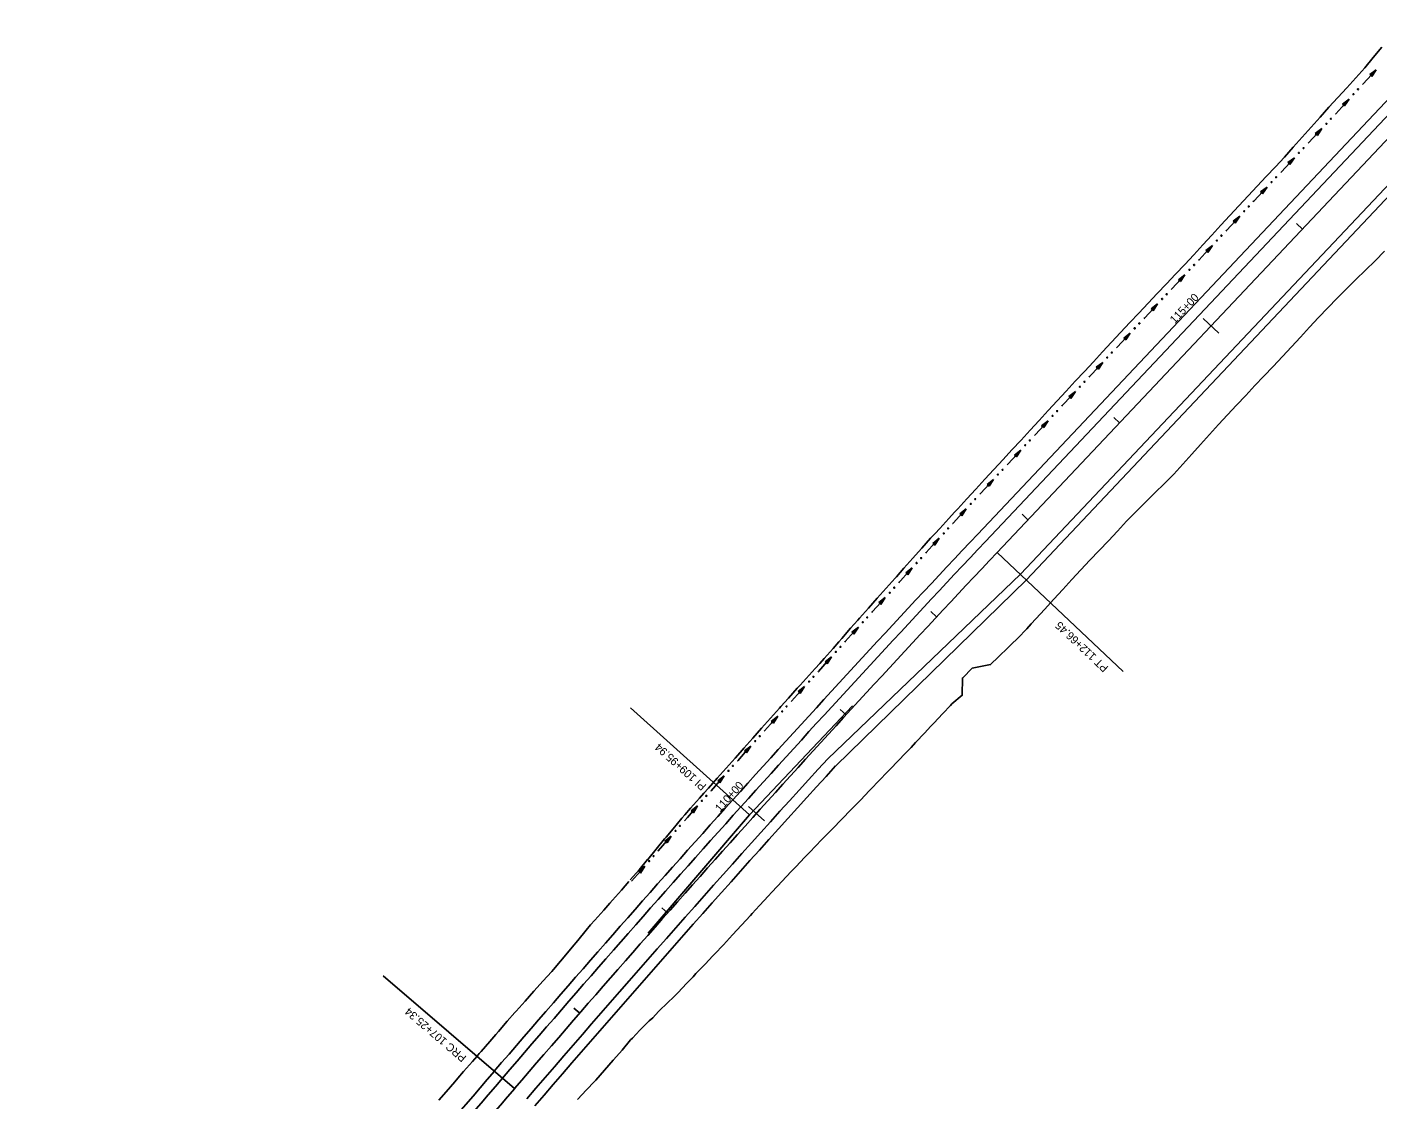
# Model space of a CAD drawing. Extents: x 1375694 to 1433473, y 1931050 to 1967991.
# Drawn here: x 1375783 to 1376795, y 1931542 to 1932347 of the extents above; entities that cross this region are included whole.
import ezdxf

# ---------------------------------------------------------------- set-up
doc = ezdxf.new("R2010")
doc.units = 0
for name, color, linetype in [('62', 7, 'Continuous'), ('R_Horz Alg', 7, 'Continuous'), ('R_Horz Alg Annot', 7, 'Continuous'), ('R_Proposed Const Limits', 7, 'Continuous'), ('R_Proposed Road', 7, 'Continuous')]:
    doc.layers.add(name, color=color, linetype=linetype)

msp = doc.modelspace()

# ---------------------------------------------------------------- linework, layer by layer
at = {"layer": '62'}
for p, q in [((1376794.8, 1932314.4), (1376789.9, 1932310.8)), ((1376789.9, 1932310.8), (1376791.5, 1932309.3)), ((1376791.5, 1932309.3), (1376794.8, 1932314.4)), ((1376774.4, 1932292.4), (1376769.5, 1932288.7)), ((1376769.5, 1932288.7), (1376771.1, 1932287.3)), ((1376771.1, 1932287.3), (1376774.4, 1932292.4)), ((1376754, 1932270.3), (1376749.1, 1932266.7)), ((1376749.1, 1932266.7), (1376750.7, 1932265.2)), ((1376750.7, 1932265.2), (1376754, 1932270.3)), ((1376733.4, 1932248.4), (1376728.6, 1932244.8)), ((1376728.6, 1932244.8), (1376730.1, 1932243.3)), ((1376730.1, 1932243.3), (1376733.4, 1932248.4)), ((1376712.9, 1932226.5), (1376708, 1932222.9)), ((1376709.6, 1932221.4), (1376712.9, 1932226.5)), ((1376708, 1932222.9), (1376709.6, 1932221.4)), ((1376692.4, 1932204.6), (1376687.5, 1932200.9)), ((1376689, 1932199.5), (1376692.4, 1932204.6)), ((1376687.5, 1932200.9), (1376689, 1932199.5)), ((1376671.9, 1932182.6), (1376667, 1932179)), ((1376667, 1932179), (1376668.5, 1932177.5)), ((1376668.5, 1932177.5), (1376671.9, 1932182.6)), ((1376651.3, 1932160.7), (1376646.5, 1932157)), ((1376646.5, 1932157), (1376648, 1932155.6)), ((1376648, 1932155.6), (1376651.3, 1932160.7)), ((1376630.8, 1932138.8), (1376625.9, 1932135.1)), ((1376625.9, 1932135.1), (1376627.5, 1932133.7)), ((1376627.5, 1932133.7), (1376630.8, 1932138.8)), ((1376610.3, 1932116.9), (1376605.4, 1932113.2)), ((1376605.4, 1932113.2), (1376606.9, 1932111.8)), ((1376606.9, 1932111.8), (1376610.3, 1932116.9)), ((1376589.7, 1932095), (1376584.8, 1932091.3)), ((1376586.4, 1932089.9), (1376589.7, 1932095)), ((1376584.8, 1932091.3), (1376586.4, 1932089.9)), ((1376569.2, 1932073), (1376564.3, 1932069.4)), ((1376565.8, 1932067.9), (1376569.2, 1932073)), ((1376564.3, 1932069.4), (1376565.8, 1932067.9)), ((1376548.7, 1932051.1), (1376543.8, 1932047.4)), ((1376543.8, 1932047.4), (1376545.4, 1932046)), ((1376545.4, 1932046), (1376548.7, 1932051.1)), ((1376528.2, 1932029.1), (1376523.4, 1932025.4)), ((1376523.4, 1932025.4), (1376524.9, 1932024)), ((1376524.9, 1932024), (1376528.2, 1932029.1)), ((1376507.8, 1932007.1), (1376502.9, 1932003.4)), ((1376502.9, 1932003.4), (1376504.5, 1932002)), ((1376504.5, 1932002), (1376507.8, 1932007.1)), ((1376487.3, 1931985.1), (1376482.5, 1931981.4)), ((1376482.5, 1931981.4), (1376484, 1931979.9)), ((1376484, 1931979.9), (1376487.3, 1931985.1)), ((1376467, 1931963), (1376462.2, 1931959.2)), ((1376463.7, 1931957.8), (1376467, 1931963)), ((1376462.2, 1931959.2), (1376463.7, 1931957.8)), ((1376446.8, 1931940.8), (1376441.9, 1931937)), ((1376443.5, 1931935.6), (1376446.8, 1931940.8)), ((1376441.9, 1931937), (1376443.5, 1931935.6)), ((1376426.6, 1931918.5), (1376421.8, 1931914.8)), ((1376421.8, 1931914.8), (1376423.3, 1931913.3)), ((1376423.3, 1931913.3), (1376426.6, 1931918.5)), ((1376406.4, 1931896.3), (1376401.5, 1931892.6)), ((1376401.5, 1931892.6), (1376403.1, 1931891.2)), ((1376403.1, 1931891.2), (1376406.4, 1931896.3)), ((1376386.2, 1931874.1), (1376381.4, 1931870.3)), ((1376381.4, 1931870.3), (1376382.9, 1931868.9)), ((1376382.9, 1931868.9), (1376386.2, 1931874.1)), ((1376366, 1931851.8), (1376361.2, 1931848)), ((1376362.8, 1931846.6), (1376366, 1931851.8)), ((1376361.2, 1931848), (1376362.8, 1931846.6)), ((1376345.9, 1931829.5), (1376341.1, 1931825.7)), ((1376342.7, 1931824.3), (1376345.9, 1931829.5)), ((1376341.1, 1931825.7), (1376342.7, 1931824.3)), ((1376325.8, 1931807.2), (1376320.9, 1931803.5)), ((1376320.9, 1931803.5), (1376322.5, 1931802)), ((1376322.5, 1931802), (1376325.8, 1931807.2)), ((1376305.7, 1931784.8), (1376301, 1931781)), ((1376301, 1931781), (1376302.5, 1931779.6)), ((1376302.5, 1931779.6), (1376305.7, 1931784.8)), ((1376285.8, 1931762.3), (1376281.1, 1931758.5)), ((1376281.1, 1931758.5), (1376282.7, 1931757.1)), ((1376282.7, 1931757.1), (1376285.8, 1931762.3)), ((1376266, 1931739.7), (1376261.3, 1931735.9)), ((1376262.9, 1931734.5), (1376266, 1931739.7)), ((1376261.3, 1931735.9), (1376262.9, 1931734.5)), ((1376246.2, 1931717.1), (1376241.5, 1931713.3)), ((1376241.5, 1931713.3), (1376243.1, 1931711.9)), ((1376243.1, 1931711.9), (1376246.2, 1931717.1))]:
    msp.add_line(p, q, dxfattribs=at)
for points in [[(1376784.6, 1932303.5), (1376784.7, 1932303.6), (1376791.5, 1932310.9), (1376794.8, 1932314.4)], [(1376784.5, 1932303.4), (1376784.6, 1932303.5)], [(1376764.2, 1932281.3), (1376764.4, 1932281.5), (1376771.2, 1932288.9), (1376774.4, 1932292.4)], [(1376764.2, 1932281.3), (1376764.2, 1932281.3)], [(1376743.7, 1932259.4), (1376743.9, 1932259.6), (1376750.8, 1932266.9), (1376754, 1932270.3)], [(1376743.7, 1932259.4), (1376743.7, 1932259.4)], [(1376723.2, 1932237.5), (1376723.4, 1932237.7), (1376730.2, 1932245), (1376733.4, 1932248.4)], [(1376723.2, 1932237.5), (1376723.2, 1932237.5)], [(1376702.6, 1932215.6), (1376702.9, 1932215.8), (1376709.7, 1932223.1), (1376712.9, 1932226.5)], [(1376702.6, 1932215.5), (1376702.6, 1932215.6)], [(1376682.1, 1932193.6), (1376682.4, 1932193.9), (1376689.2, 1932201.2), (1376692.4, 1932204.6)], [(1376682.1, 1932193.6), (1376682.1, 1932193.6)], [(1376661.6, 1932171.7), (1376661.9, 1932172), (1376668.7, 1932179.3), (1376671.9, 1932182.6)], [(1376661.6, 1932171.6), (1376661.6, 1932171.7)], [(1376641.1, 1932149.7), (1376641.4, 1932150.1), (1376648.2, 1932157.4), (1376651.3, 1932160.7)], [(1376641.1, 1932149.7), (1376641.1, 1932149.7)], [(1376620.5, 1932127.8), (1376620.9, 1932128.2), (1376627.7, 1932135.5), (1376630.8, 1932138.8)], [(1376620.5, 1932127.8), (1376620.5, 1932127.8)], [(1376600, 1932105.9), (1376600.4, 1932106.3), (1376607.2, 1932113.6), (1376610.3, 1932116.9)], [(1376600, 1932105.9), (1376600, 1932105.9)], [(1376579.4, 1932084), (1376579.8, 1932084.4), (1376586.7, 1932091.7), (1376589.7, 1932095)], [(1376579.4, 1932084), (1376579.4, 1932084)], [(1376558.9, 1932062.1), (1376559.3, 1932062.5), (1376566.2, 1932069.8), (1376569.2, 1932073)], [(1376558.9, 1932062.1), (1376558.9, 1932062.1)], [(1376538.4, 1932040.1), (1376538.9, 1932040.6), (1376545.7, 1932047.9), (1376548.7, 1932051.1)], [(1376538.4, 1932040.1), (1376538.4, 1932040.1)], [(1376518, 1932018.1), (1376518.5, 1932018.6), (1376525.3, 1932025.9), (1376528.2, 1932029.1)], [(1376518, 1932018.1), (1376518, 1932018.1)], [(1376497.6, 1931996.1), (1376498, 1931996.6), (1376504.8, 1932003.9), (1376507.8, 1932007.1)], [(1376497.5, 1931996.1), (1376497.6, 1931996.1)], [(1376477.2, 1931974), (1376477.7, 1931974.6), (1376482, 1931979.3), (1376484.4, 1931982), (1376487.3, 1931985.1)], [(1376477.1, 1931974), (1376477.2, 1931974)], [(1376456.9, 1931951.9), (1376457.3, 1931952.4), (1376464.1, 1931959.8), (1376467, 1931963)], [(1376456.9, 1931951.9), (1376456.9, 1931951.9)], [(1376436.7, 1931929.7), (1376437.1, 1931930.1), (1376438.1, 1931931.2), (1376443.8, 1931937.5), (1376446.8, 1931940.8)], [(1376436.7, 1931929.6), (1376436.7, 1931929.7)], [(1376416.5, 1931907.4), (1376416.8, 1931907.8), (1376423.5, 1931915.1), (1376423.6, 1931915.2), (1376426.6, 1931918.5)], [(1376416.5, 1931907.4), (1376416.5, 1931907.4)], [(1376396.3, 1931885.2), (1376396.6, 1931885.6), (1376403.3, 1931893), (1376406.4, 1931896.3)], [(1376396.2, 1931885.2), (1376396.3, 1931885.2)], [(1376376.1, 1931862.9), (1376376.4, 1931863.2), (1376379.7, 1931866.9), (1376383.1, 1931870.7), (1376386.2, 1931874.1)], [(1376376.1, 1931862.9), (1376376.1, 1931862.9)], [(1376356, 1931840.6), (1376356.2, 1931840.9), (1376362.9, 1931848.3), (1376365.2, 1931850.8), (1376366, 1931851.8)], [(1376356, 1931840.6), (1376356, 1931840.6)], [(1376335.8, 1931818.3), (1376336, 1931818.6), (1376336, 1931818.6), (1376342.8, 1931826), (1376345.9, 1931829.5)], [(1376335.8, 1931818.3), (1376335.8, 1931818.3)], [(1376315.7, 1931796.1), (1376315.9, 1931796.2), (1376321.5, 1931802.5), (1376322.6, 1931803.7), (1376325.8, 1931807.2)], [(1376315.7, 1931796), (1376315.7, 1931796.1)], [(1376295.8, 1931773.6), (1376295.9, 1931773.7), (1376302.5, 1931781.2), (1376305.7, 1931784.8)], [(1376295.8, 1931773.5), (1376295.8, 1931773.6)], [(1376275.9, 1931751), (1376276, 1931751.1), (1376278.3, 1931753.7), (1376282.6, 1931758.6), (1376285.8, 1931762.3)], [(1376275.9, 1931751), (1376275.9, 1931751)], [(1376256.1, 1931728.4), (1376256.2, 1931728.5), (1376262.8, 1931736), (1376264, 1931737.4), (1376266, 1931739.7)], [(1376256.1, 1931728.4), (1376256.1, 1931728.4)], [(1376236.3, 1931705.9), (1376243, 1931713.4), (1376246.2, 1931717.1)]]:
    msp.add_lwpolyline(points, dxfattribs=at)
for centre in [(1376777.7, 1932296.1), (1376781.1, 1932299.8), (1376757.4, 1932274), (1376760.8, 1932277.7), (1376740.3, 1932255.7), (1376736.8, 1932252.1), (1376719.7, 1932233.8), (1376716.3, 1932230.2), (1376695.8, 1932208.3), (1376699.2, 1932211.9), (1376675.3, 1932186.3), (1376678.7, 1932190), (1376654.7, 1932164.4), (1376658.2, 1932168), (1376634.2, 1932142.5), (1376637.6, 1932146.1), (1376617.1, 1932124.2), (1376613.6, 1932120.5), (1376596.5, 1932102.3), (1376593.1, 1932098.6), (1376572.6, 1932076.7), (1376576, 1932080.4), (1376552.1, 1932054.8), (1376555.5, 1932058.4), (1376531.6, 1932032.8), (1376535, 1932036.4), (1376511.1, 1932010.8), (1376514.6, 1932014.4), (1376494.1, 1931992.4), (1376490.7, 1931988.8), (1376473.7, 1931970.4), (1376470.4, 1931966.7), (1376450.1, 1931944.5), (1376453.5, 1931948.2), (1376429.9, 1931922.2), (1376433.3, 1931926), (1376409.7, 1931900), (1376413.1, 1931903.7), (1376392.9, 1931881.5), (1376389.5, 1931877.8), (1376372.7, 1931859.2), (1376369.4, 1931855.5), (1376349.3, 1931833.2), (1376352.6, 1931836.9), (1376329.1, 1931810.9), (1376332.4, 1931814.6), (1376309, 1931788.6), (1376312.3, 1931792.3), (1376292.4, 1931769.8), (1376289.1, 1931766.1), (1376269.3, 1931743.5), (1376272.6, 1931747.3), (1376249.5, 1931720.9), (1376252.8, 1931724.7)]:
    msp.add_circle(centre, 0.375, dxfattribs=at)
at = {"layer": 'R_Horz Alg'}
msp.add_line((1376510.6, 1931952.4), (1377531.3, 1933034.1), dxfattribs=at)
for centre, start, end in [((1384844.8, 1924087.8), 136.66069, 139.36624), ((1367452.4, 1939012.7), 316.73955, 319.36624)]:
    msp.add_arc(centre, 11459.2, start, end, dxfattribs=at)
at = {"layer": 'R_Horz Alg Annot'}
for p, q in [((1376402, 1931837.4), (1376324.8, 1931755.6)), ((1376324.8, 1931755.6), (1376248.7, 1931666.9))]:
    msp.add_line(p, q, dxfattribs=at)
for points in [[(1376735.1, 1932199.1), (1376739.5, 1932195)], [(1376665, 1932127.8), (1376676.7, 1932116.8)], [(1376597.9, 1932053.7), (1376602.2, 1932049.6)], [(1376529.2, 1931981), (1376533.6, 1931976.8)], [(1376510.6, 1931952.4), (1376605.1, 1931863.2)], [(1376460.7, 1931908.1), (1376465.1, 1931904)], [(1376324.8, 1931755.6), (1376235.6, 1931835.9)], [(1376392.8, 1931834.6), (1376397.2, 1931830.5)], [(1376324, 1931761.9), (1376335.9, 1931751.2)], [(1376258.9, 1931685.9), (1376263.4, 1931681.9)], [(1376148.6, 1931550.3), (1376050, 1931634.9)], [(1376192.9, 1931610.7), (1376197.4, 1931606.8)]]:
    msp.add_lwpolyline(points, dxfattribs=at)
at = {"layer": 'R_Proposed Const Limits'}
for points in [[(1376235.2, 1931706.9), (1376241.9, 1931714.4), (1376248.3, 1931722.1), (1376248.4, 1931722.2), (1376254.7, 1931729.8), (1376261.1, 1931737.5), (1376262.3, 1931738.9), (1376267.5, 1931745.2), (1376273.9, 1931753), (1376276.2, 1931755.6), (1376280.5, 1931760.5), (1376287.2, 1931768), (1376290.6, 1931771.8), (1376293.9, 1931775.5), (1376300.5, 1931783), (1376305, 1931788.1), (1376307.2, 1931790.5), (1376313.9, 1931798), (1376319.4, 1931804.3), (1376320.5, 1931805.5), (1376327.2, 1931813.1), (1376333.8, 1931820.6), (1376333.8, 1931820.6), (1376340.5, 1931828.1), (1376347.2, 1931835.5), (1376348.3, 1931836.8), (1376353.9, 1931843), (1376360.6, 1931850.5), (1376362.8, 1931852.9), (1376367.3, 1931857.9), (1376374, 1931865.4), (1376377.4, 1931869.1), (1376380.8, 1931872.8), (1376387.4, 1931880.4), (1376391.7, 1931885.4), (1376394, 1931887.9), (1376400.6, 1931895.5), (1376406.1, 1931901.7), (1376407.3, 1931903), (1376413.9, 1931910.5), (1376420.5, 1931918), (1376420.6, 1931918.1), (1376427.2, 1931925.6), (1376433.9, 1931933.1), (1376434.9, 1931934.2), (1376440.5, 1931940.6), (1376447.2, 1931948.1), (1376449.3, 1931950.4), (1376453.9, 1931955.6), (1376460.6, 1931963), (1376463.9, 1931966.6), (1376467.4, 1931970.4), (1376474.2, 1931977.9), (1376478.5, 1931982.6), (1376481, 1931985.2), (1376487.7, 1931992.6), (1376494.5, 1931999.9), (1376501.3, 1932007.3), (1376508.1, 1932014.6), (1376514.9, 1932022), (1376521.6, 1932029.4), (1376528.4, 1932036.7), (1376535.2, 1932044.1), (1376542, 1932051.4), (1376548.8, 1932058.8), (1376555.5, 1932066.1), (1376562.3, 1932073.4), (1376569.1, 1932080.8), (1376575.9, 1932088.1), (1376582.7, 1932095.5), (1376589.5, 1932102.8), (1376596.3, 1932110.1), (1376603.1, 1932117.5), (1376609.9, 1932124.8), (1376616.8, 1932132), (1376623.7, 1932139.3), (1376630.6, 1932146.6), (1376637.4, 1932153.8), (1376644.3, 1932161.1), (1376651.2, 1932168.4), (1376657.9, 1932175.7), (1376664.7, 1932183.1), (1376671.5, 1932190.4), (1376678.2, 1932197.8), (1376685, 1932205.2), (1376691.8, 1932212.5), (1376698.7, 1932219.8), (1376705.5, 1932227.1), (1376712.3, 1932234.4), (1376719.2, 1932241.7), (1376726, 1932249), (1376732.6, 1932256.5), (1376739.3, 1932263.9), (1376746.1, 1932271.3), (1376752.7, 1932278.8), (1376759.3, 1932286.3), (1376766.1, 1932293.7), (1376772.8, 1932301), (1376779.5, 1932308.5), (1376786.2, 1932315.9), (1376792.5, 1932323.7), (1376799.1, 1932331.3)], [(1376491.8, 1931865.5), (1376505.5, 1931868.3), (1376511.6, 1931874.2), (1376518.8, 1931881.1), (1376521, 1931883.3), (1376525.9, 1931888.1), (1376532.8, 1931895.2), (1376536, 1931898.8), (1376539.5, 1931902.6), (1376546.3, 1931909.9), (1376550.6, 1931914.7), (1376553, 1931917.3), (1376559.7, 1931924.7), (1376566.5, 1931932.1), (1376573.2, 1931939.4), (1376580.1, 1931946.7), (1376587, 1931953.9), (1376594, 1931961.1), (1376600.8, 1931968.4), (1376607.5, 1931975.8), (1376614.6, 1931982.9), (1376621.7, 1931990), (1376628.8, 1931997), (1376635.9, 1932004.1), (1376643, 1932011.1), (1376649.7, 1932018.5), (1376656.4, 1932026), (1376663, 1932033.4), (1376669.7, 1932040.9), (1376676.4, 1932048.3), (1376683.2, 1932055.6), (1376690.1, 1932062.9), (1376696.9, 1932070.2), (1376703.8, 1932077.5), (1376710.6, 1932084.7), (1376717.5, 1932092), (1376724.4, 1932099.3), (1376731.2, 1932106.6), (1376738, 1932113.9), (1376744.8, 1932121.3), (1376751.6, 1932128.6), (1376758.4, 1932135.9), (1376765.4, 1932143.1), (1376772.4, 1932150.2), (1376779.6, 1932157.2), (1376786.7, 1932164.2), (1376793.9, 1932171.2), (1376800.9, 1932178.3)], [(1376484.6, 1931858.4), (1376484.7, 1931858.4), (1376491.8, 1931865.5)], [(1376195.8, 1931542.1), (1376202.6, 1931549.4), (1376208.6, 1931555.7), (1376209.5, 1931556.7), (1376216, 1931564.2), (1376222.5, 1931571.7), (1376222.7, 1931571.9), (1376229.3, 1931579.1), (1376235.6, 1931586.8), (1376236.9, 1931588.2), (1376242.5, 1931594), (1376249.6, 1931601), (1376252.2, 1931603.4), (1376256.6, 1931608.1), (1376263.8, 1931615.1), (1376267.6, 1931618.6), (1376270.9, 1931622.1), (1376277.8, 1931629.3), (1376282.5, 1931634.2), (1376284.6, 1931636.5), (1376291.5, 1931643.7), (1376297.3, 1931649.9), (1376298.4, 1931651), (1376305.2, 1931658.2), (1376312, 1931665.5), (1376312.1, 1931665.6), (1376318.7, 1931672.8), (1376325.5, 1931680.2), (1376326.7, 1931681.5), (1376332.2, 1931687.5), (1376338.9, 1931694.8), (1376341.2, 1931697.4), (1376345.7, 1931702.1), (1376352.6, 1931709.4), (1376356.1, 1931713), (1376359.5, 1931716.6), (1376366.3, 1931723.8), (1376371, 1931728.6), (1376373.2, 1931731), (1376380.1, 1931738.2), (1376386, 1931744.1), (1376387.1, 1931745.2), (1376394, 1931752.4), (1376401, 1931759.5), (1376401, 1931759.5), (1376407.9, 1931766.7), (1376414.8, 1931773.9), (1376416, 1931775.1), (1376421.7, 1931781.1), (1376428.6, 1931788.2), (1376430.9, 1931790.6), (1376435.6, 1931795.4), (1376442.5, 1931802.5), (1376445.9, 1931806.1), (1376449.3, 1931809.8), (1376456.2, 1931817), (1376460.6, 1931821.8), (1376463, 1931824.3), (1376469.8, 1931831.5), (1376475.4, 1931837.5), (1376476.6, 1931838.8), (1376484.3, 1931845.3), (1376484.6, 1931858.4)], [(1376091.7, 1931541.6), (1376097.2, 1931547.9), (1376103.8, 1931555.4), (1376106.1, 1931558), (1376110.3, 1931563), (1376116.9, 1931570.5), (1376120.4, 1931574.5), (1376122.1, 1931576.5), (1376123.4, 1931578), (1376130, 1931585.6), (1376134.5, 1931590.9), (1376136.5, 1931593.2), (1376143.1, 1931600.8), (1376148.8, 1931607.3), (1376149.7, 1931608.4), (1376156.4, 1931615.8), (1376163.1, 1931623.3), (1376163.2, 1931623.5), (1376169.8, 1931630.8), (1376176.5, 1931638.2), (1376177.8, 1931639.7), (1376183, 1931645.8), (1376189.5, 1931653.5), (1376191.8, 1931656.3), (1376195.9, 1931661.3), (1376202.3, 1931669), (1376205.6, 1931673.1), (1376208.8, 1931676.7), (1376215.4, 1931684.2), (1376219.9, 1931689.3), (1376222, 1931691.7), (1376228.7, 1931699.2), (1376234.3, 1931705.6)]]:
    msp.add_lwpolyline(points, dxfattribs=at)
at = {"layer": 'R_Proposed Road'}
for p, q in [((1376496, 1931966.2), (1377516.7, 1933047.9)), ((1376501.8, 1931960.7), (1377522.6, 1933042.4)), ((1376528, 1931936), (1377548.7, 1933017.7)), ((1376532.4, 1931931.8), (1377553.1, 1933013.5)), ((1376383.4, 1931797.7), (1376528, 1931936)), ((1376389.4, 1931792.3), (1376532.4, 1931931.8))]:
    msp.add_line(p, q, dxfattribs=at)
for centre, radius, start, end in [((1384844.8, 1924087.8), 11479.2, 136.66069, 139.36624), ((1384844.8, 1924087.8), 11471.2, 136.66069, 139.36624), ((1384844.8, 1924087.8), 11447.2, 137.66069, 139.36624), ((1384844.8, 1924087.8), 11439.2, 137.66069, 139.36624), ((1367452.4, 1939012.7), 11439.2, 316.73955, 319.36624), ((1367452.4, 1939012.7), 11447.2, 316.73955, 319.36624)]:
    msp.add_arc(centre, radius, start, end, dxfattribs=at)

# ---------------------------------------------------------------- texts
at = {"layer": 'R_Horz Alg'}
for rotation, p in [(46.6607, (1376510.6, 1931951.8)), (49.3662, (1376148.7, 1931549.6))]:
    msp.add_text('+', height=1, rotation=rotation, dxfattribs=at).set_placement(p)
at = {"layer": 'R_Horz Alg Annot'}
for s, rotation, p in [('115+00', 46.6607, (1376643.7, 1932123.6)), ('PT 112+66.45', 136.6607, (1376594.4, 1931866.4)), ('PI 109+95.94', 138.0135, (1376292.8, 1931777.7)), ('110+00', 47.9929, (1376302.7, 1931757.3)), ('PRC 107+25.34', 139.3662, (1376113, 1931574.2))]:
    msp.add_text(s, height=6, rotation=rotation, dxfattribs=at).set_placement(p)

doc.saveas('drawing.dxf')
